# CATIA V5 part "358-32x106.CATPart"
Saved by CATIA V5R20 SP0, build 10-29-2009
Part number: 358-32X106
Definition: NONE
Nomenclature: 358-32X106
Source: Unknown
Description: 358-32X106
Bounding box of the stored display mesh (mm): x -17 to 89, y -22.5 to 22.5, z -22.5 to 22.5
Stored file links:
  C:\Users\Utente\Desktop\IO LAVORO\3D X SITO CF\X SITO\PLASTICA\358\358-32x106.CATPart
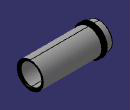
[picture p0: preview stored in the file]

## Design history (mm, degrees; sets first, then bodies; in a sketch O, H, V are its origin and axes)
Body1 "358-32X106" (main body)
  Solid1: solid without history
